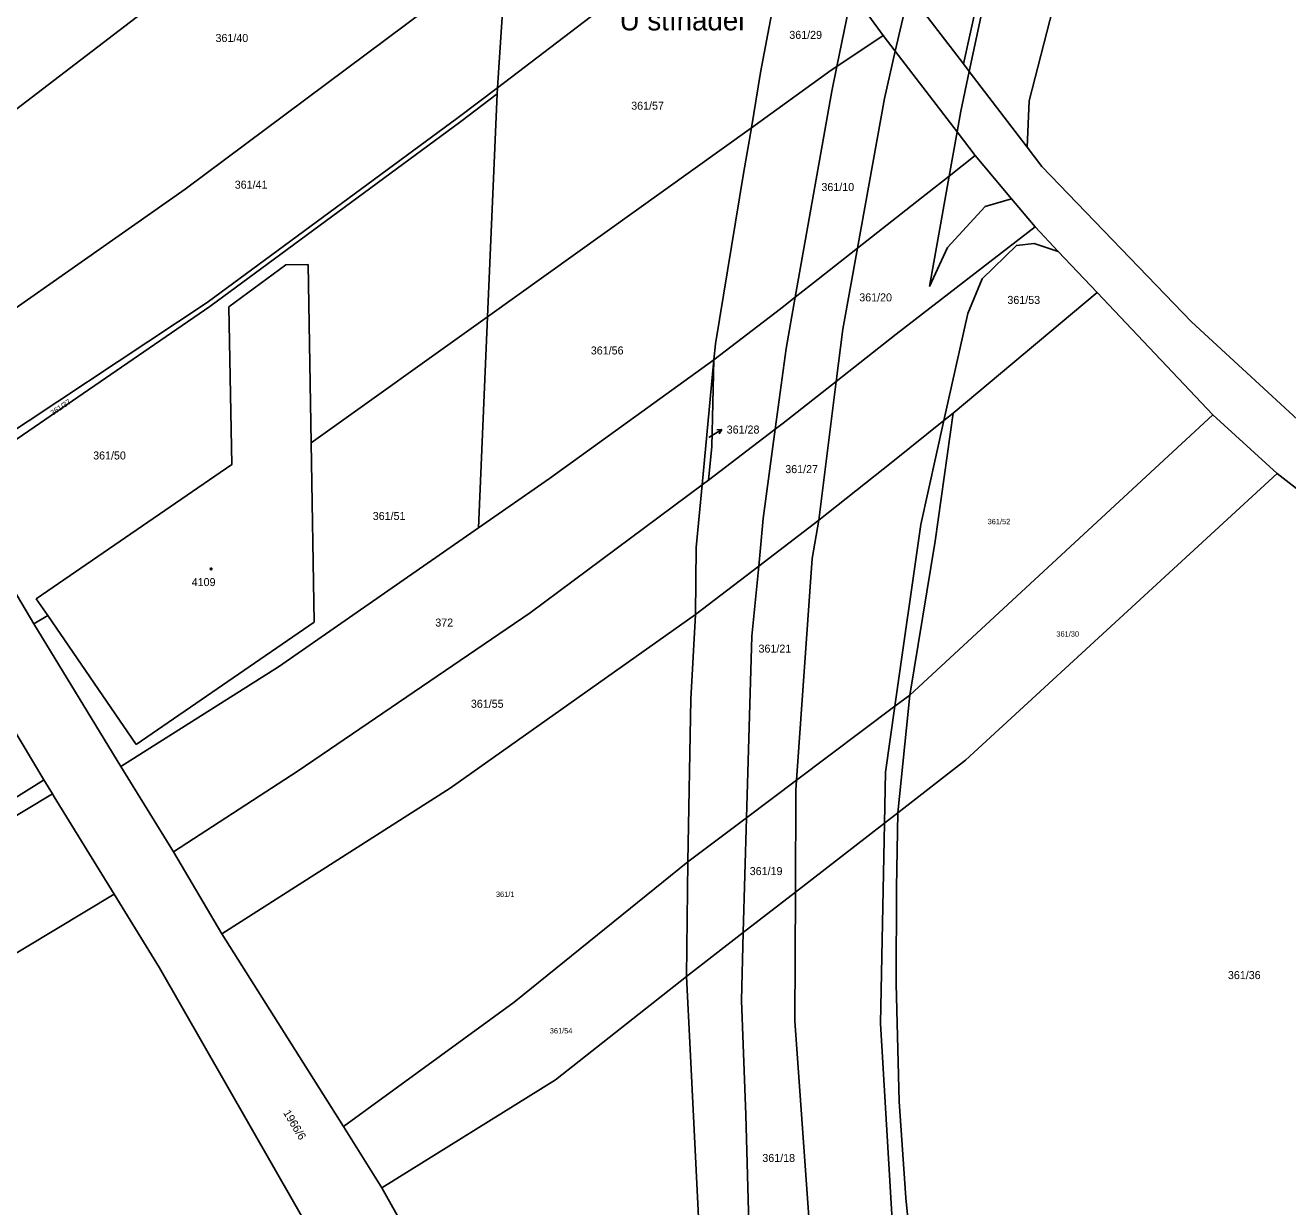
# Model space of a CAD drawing. Extents: x -679220 to -673243, y -1075091 to -1066557.
# Drawn here: x -675653.7 to -675385.5, y -1072806.7 to -1072555.7 of the extents above; entities that cross this region are included whole.
import ezdxf

# ---------------------------------------------------------------- set-up
doc = ezdxf.new("R2010")
doc.units = 0
for name, color, linetype in [('Hranice parcel', 7, 'Continuous'), ('Parcelní čísla', 7, 'Continuous'), ('Pop  PČ popisy', 7, 'Continuous'), ('Vnitřní kresba', 7, 'Continuous'), ('Značky budov', 7, 'Continuous')]:
    doc.layers.add(name, color=color, linetype=linetype)

msp = doc.modelspace()

# ---------------------------------------------------------------- linework, layer by layer
at = {"layer": 'Hranice parcel'}
for p, q in [((-675553.38, -1072569.02), (-675495.78, -1072525.1)), ((-675553.38, -1072569.02), (-675551.48, -1072539.61)), ((-675453.16, -1072565.56), (-675454.36, -1072563.91)), ((-675440.85, -1072581.63), (-675453.16, -1072565.56)), ((-675555.5, -1072617.65), (-675553.46, -1072570.33)), ((-675553.38, -1072569.02), (-675553.46, -1072570.33)), ((-675440.45, -1072571.81), (-675440.85, -1072581.63)), ((-675499.44, -1072577.56), (-675555.5, -1072617.65)), ((-675455.75, -1072578.38), (-675451.87, -1072583.44)), ((-675439.14, -1072598.56), (-675434.25, -1072603.83)), ((-675434.25, -1072603.83), (-675426.02, -1072612.52)), ((-675593.59, -1072606.56), (-675592.95, -1072644.44)), ((-675426.02, -1072612.52), (-675456.55, -1072638.11)), ((-675426.02, -1072612.52), (-675401.43, -1072638.52)), ((-675592.95, -1072644.44), (-675555.5, -1072617.65)), ((-675557.43, -1072662.47), (-675555.5, -1072617.65)), ((-675509.93, -1072653.38), (-675507.45, -1072626.81)), ((-675401.43, -1072638.52), (-675465.82, -1072698.04)), ((-675456.55, -1072638.11), (-675458.55, -1072639.71)), ((-675401.43, -1072638.52), (-675387.75, -1072650.99)), ((-675592.95, -1072644.44), (-675592.3, -1072682.51)), ((-675508.55, -1072652.36), (-675509.93, -1072653.38)), ((-675651.88, -1072682.89), (-675663.08, -1072664)), ((-675648.95, -1072681.1), (-675651.36, -1072677.58)), ((-675651.88, -1072682.89), (-675648.95, -1072681.1)), ((-675630.15, -1072708.51), (-675648.95, -1072681.1)), ((-675633.38, -1072713.17), (-675651.88, -1072682.89)), ((-675592.3, -1072682.51), (-675630.15, -1072708.51)), ((-675649.73, -1072716.03), (-675659.26, -1072700.21)), ((-675468.34, -1072723.01), (-675465.82, -1072698.04)), ((-675622.22, -1072731.3), (-675633.38, -1072713.17)), ((-675647.93, -1072719.02), (-675649.73, -1072716.03)), ((-675611.95, -1072748.75), (-675622.22, -1072731.3)), ((-675513.21, -1072757.8), (-675512.92, -1072733.44)), ((-675634.82, -1072740.31), (-675691.64, -1072774.4)), ((-675611.95, -1072748.75), (-675586.09, -1072789.66)), ((-675577.95, -1072802.67), (-675586.09, -1072789.66))]:
    msp.add_line(p, q, dxfattribs=at)
for points in [[(-675454.36, -1072563.91), (-675446, -1072526.06), (-675439.38, -1072499.72)], [(-675487.9, -1072519.25), (-675485.11, -1072523), (-675475.5, -1072535.97), (-675466.02, -1072548.77), (-675454.36, -1072563.91)], [(-675453.16, -1072565.56), (-675444.4, -1072524.55), (-675443.75, -1072521.35)], [(-675437.14, -1072522.7), (-675432.4, -1072525.63), (-675433.53, -1072545.05), (-675440.45, -1072571.81)], [(-675594.8, -1072523.34), (-675593.03, -1072525.66), (-675664.03, -1072579.96), (-675667.06, -1072576)], [(-675499.44, -1072577.56), (-675497.51, -1072565.78), (-675490.93, -1072531.03)], [(-675471.44, -1072557.92), (-675478.09, -1072548.74), (-675490.93, -1072531.03)], [(-675681.36, -1072633.74), (-675619.75, -1072590.56), (-675551.48, -1072539.61)], [(-675471.44, -1072557.92), (-675481.29, -1072564.52), (-675482.48, -1072565.31), (-675499.44, -1072577.56)], [(-675455.75, -1072578.38), (-675468.88, -1072561.25), (-675471.44, -1072557.92)], [(-675453.16, -1072565.56), (-675454.96, -1072573.97), (-675455.75, -1072578.38)], [(-675665.8, -1072648.21), (-675615.05, -1072614.65), (-675561.74, -1072575.37), (-675553.38, -1072569.02)], [(-675553.46, -1072570.33), (-675561.17, -1072576.17), (-675614.5, -1072615.46), (-675664.77, -1072649.96)], [(-675507.45, -1072626.81), (-675507.05, -1072623.4), (-675501.11, -1072587.23), (-675499.44, -1072577.56)], [(-675370.78, -1072651.18), (-675405.96, -1072618.74), (-675437.71, -1072585.73), (-675440.85, -1072581.63)], [(-675507.45, -1072626.81), (-675493.27, -1072615.98), (-675490.14, -1072613.53), (-675485.23, -1072609.68), (-675476.93, -1072603.13), (-675462.32, -1072591.61), (-675457.44, -1072587.79), (-675451.87, -1072583.44)], [(-675451.87, -1072583.44), (-675444.17, -1072592.59), (-675439.14, -1072598.56)], [(-675508.55, -1072652.36), (-675494.37, -1072641.56), (-675492.68, -1072640.27), (-675481.42, -1072631.41), (-675468.68, -1072621.39), (-675439.14, -1072598.56)], [(-675458.55, -1072639.71), (-675453.48, -1072616.98), (-675450.39, -1072609.61), (-675443.14, -1072602.51), (-675439.34, -1072602.07), (-675434.25, -1072603.83)], [(-675651.36, -1072677.58), (-675609.86, -1072649.07), (-675610.44, -1072615.56), (-675598.36, -1072606.66), (-675593.59, -1072606.56)], [(-675557.43, -1072662.47), (-675542.36, -1072651.99), (-675507.45, -1072626.81)], [(-675507.45, -1072626.81), (-675507.84, -1072645.19), (-675508.55, -1072652.36)], [(-675465.82, -1072698.04), (-675460.43, -1072665.36), (-675456.55, -1072638.11)], [(-675458.55, -1072639.71), (-675469.42, -1072648.43), (-675485.13, -1072660.87), (-675497.89, -1072670.62), (-675511.33, -1072680.88)], [(-675387.75, -1072650.99), (-675453.98, -1072711.83), (-675468.34, -1072723.01)], [(-675387.75, -1072650.99), (-675367.76, -1072666.49), (-675351.82, -1072681.46), (-675300.01, -1072726.38), (-675290.4, -1072737.5)], [(-675509.93, -1072653.38), (-675546.47, -1072680.57), (-675595.74, -1072714.13), (-675622.22, -1072731.3)], [(-675511.33, -1072680.88), (-675511.16, -1072666.66), (-675509.93, -1072653.38)], [(-675633.38, -1072713.17), (-675599.94, -1072692.01), (-675557.43, -1072662.47)], [(-675511.33, -1072680.88), (-675563.46, -1072717.8), (-675611.95, -1072748.75)], [(-675512.92, -1072733.44), (-675512.32, -1072698.86), (-675511.33, -1072680.88)], [(-675465.82, -1072698.04), (-675468.97, -1072700.4), (-675489.84, -1072716.09), (-675500.46, -1072724.07), (-675512.92, -1072733.44)], [(-675678.86, -1072730.74), (-675672.92, -1072730.51), (-675649.87, -1072716.12), (-675649.73, -1072716.03)], [(-675692.39, -1072742.99), (-675681.03, -1072738.1), (-675671.48, -1072733.15), (-675647.93, -1072719.02)], [(-675647.93, -1072719.02), (-675647.56, -1072719.64), (-675634.82, -1072740.31)], [(-675468.34, -1072723.01), (-675471.17, -1072725.2), (-675490.08, -1072739.87), (-675501.16, -1072748.45), (-675513.21, -1072757.8)], [(-675448.52, -1072908.9), (-675449.85, -1072906.74), (-675452.49, -1072898.87), (-675458.7, -1072868), (-675462.64, -1072845.24), (-675466.61, -1072804.78), (-675468.02, -1072784.34), (-675468.66, -1072759.35), (-675468.62, -1072738.95), (-675468.34, -1072723.01)], [(-675586.09, -1072789.66), (-675549.83, -1072763.23), (-675512.92, -1072733.44)], [(-675634.82, -1072740.31), (-675625.19, -1072755.93), (-675586.95, -1072822.71), (-675573.11, -1072845.8)], [(-675577.95, -1072802.67), (-675541.03, -1072779.72), (-675513.21, -1072757.8)], [(-675513.21, -1072757.8), (-675512.46, -1072773.25), (-675510.33, -1072816.05), (-675507.9, -1072853.17), (-675504.88, -1072880.03)], [(-675565.89, -1072823.51), (-675571.67, -1072813.96), (-675577.95, -1072802.67)]]:
    msp.add_lwpolyline(points, dxfattribs=at)
at = {"layer": 'Pop  PČ popisy'}
for p, q in [((-675508.48, -1072643.28), (-675508.27, -1072643.15)), ((-675508.27, -1072643.15), (-675505.7, -1072641.6)), ((-675505.7, -1072641.6), (-675506.81, -1072641.69)), ((-675505.7, -1072641.6), (-675506.3, -1072642.55))]:
    msp.add_line(p, q, dxfattribs=at)
at = {"layer": 'Vnitřní kresba'}
for p, q in [((-675478.09, -1072548.74), (-675481.29, -1072564.52)), ((-675466.02, -1072548.77), (-675468.88, -1072561.25)), ((-675468.88, -1072561.25), (-675471.19, -1072571.31)), ((-675481.29, -1072564.52), (-675482.35, -1072569.72)), ((-675490.14, -1072613.53), (-675482.35, -1072569.72)), ((-675476.93, -1072603.13), (-675471.19, -1072571.31)), ((-675457.44, -1072587.79), (-675455.75, -1072578.38)), ((-675461.64, -1072611.25), (-675457.44, -1072587.79)), ((-675444.17, -1072592.59), (-675449.75, -1072594.28)), ((-675449.75, -1072594.28), (-675457.76, -1072602.97)), ((-675480.02, -1072620.28), (-675476.93, -1072603.13)), ((-675457.76, -1072602.97), (-675461.64, -1072611.25)), ((-675492.07, -1072624.39), (-675490.14, -1072613.53)), ((-675480.02, -1072620.28), (-675481.42, -1072631.41)), ((-675494.37, -1072641.56), (-675492.07, -1072624.39)), ((-675481.42, -1072631.41), (-675485.13, -1072660.87)), ((-675458.55, -1072639.71), (-675463.47, -1072661.76)), ((-675496.91, -1072660.54), (-675494.37, -1072641.56)), ((-675497.89, -1072670.62), (-675496.91, -1072660.54)), ((-675485.13, -1072660.87), (-675486.54, -1072669.03)), ((-675468.97, -1072700.4), (-675463.47, -1072661.76)), ((-675499.35, -1072685.52), (-675497.89, -1072670.62)), ((-675486.54, -1072669.03), (-675489.84, -1072716.09)), ((-675500.46, -1072724.07), (-675499.35, -1072685.52)), ((-675470.96, -1072714.43), (-675468.97, -1072700.4)), ((-675489.84, -1072716.09), (-675489.99, -1072718.24)), ((-675471.17, -1072725.2), (-675470.96, -1072714.43)), ((-675490.08, -1072739.87), (-675489.99, -1072718.24)), ((-675501.16, -1072748.45), (-675500.46, -1072724.07)), ((-675471.99, -1072767.75), (-675471.17, -1072725.2)), ((-675490.2, -1072767.27), (-675490.08, -1072739.87)), ((-675501.57, -1072762.93), (-675501.16, -1072748.45)), ((-675500.64, -1072787.2), (-675501.57, -1072762.93)), ((-675490.2, -1072767.27), (-675486.67, -1072816.73)), ((-675471.99, -1072767.75), (-675469.47, -1072810.74)), ((-675499.49, -1072827.02), (-675500.64, -1072787.2))]:
    msp.add_line(p, q, dxfattribs=at)
at = {"layer": 'Značky budov'}
msp.add_circle((-675614.22, -1072671.21), 0.175, dxfattribs=at)

# ---------------------------------------------------------------- texts
at = {"layer": 'Parcelní čísla'}
for s, height, p in [('361/40', 1.7, (-675613.29, -1072559.3)), ('361/29', 1.7, (-675491.39, -1072558.64)), ('361/57', 1.7, (-675524.98, -1072573.68)), ('361/41', 1.7, (-675609.21, -1072590.46)), ('361/10', 1.7, (-675484.57, -1072590.95)), ('361/20', 1.7, (-675476.53, -1072614.4)), ('361/53', 1.7, (-675445.06, -1072614.94)), ('361/56', 1.7, (-675533.56, -1072625.67)), ('361/28', 1.7, (-675504.69, -1072642.47)), ('361/50', 1.7, (-675639.29, -1072647.98)), ('361/27', 1.7, (-675492.25, -1072650.88)), ('361/51', 1.7, (-675579.89, -1072660.83)), ('361/52', 1.14, (-675449.26, -1072661.73)), ('4109', 1.7, (-675618.35, -1072674.87)), ('372', 1.7, (-675566.6, -1072683.47)), ('361/30', 1.14, (-675434.65, -1072685.61)), ('361/21', 1.7, (-675497.93, -1072689)), ('361/55', 1.7, (-675559.04, -1072700.72)), ('361/19', 1.7, (-675499.8, -1072736.26)), ('361/1', 1.14, (-675553.72, -1072740.9)), ('361/36', 1.7, (-675398.21, -1072758.35)), ('361/54', 1.14, (-675542.28, -1072769.89)), ('361/18', 1.7, (-675497.12, -1072797.19))]:
    msp.add_text(s, height=height, dxfattribs=at).set_placement(p)
for s, height, rotation, p in [('361/37', 1.14, 34, (-675647.9, -1072638.7)), ('1966/6', 1.7, 301, (-675598.98, -1072786.74))]:
    msp.add_text(s, height=height, rotation=rotation, dxfattribs=at).set_placement(p)
at = {"layer": 'Pop  PČ popisy'}
msp.add_text('U stínadel', height=4.4, dxfattribs=at).set_placement((-675527.43, -1072556.84))

doc.saveas('drawing.dxf')
